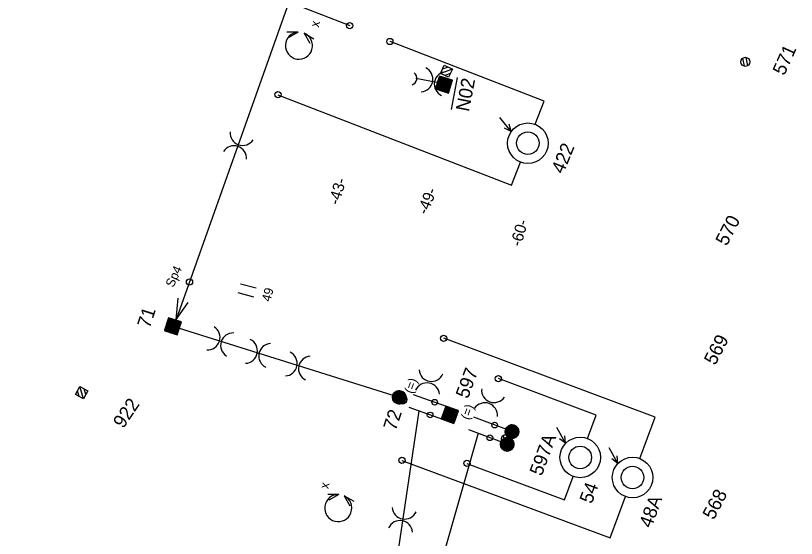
# Model space of a CAD drawing. Extents: x -595867 to -593796, y -1159595 to -1157495.
# Drawn here: x -594730.7 to -594644.3, y -1157983.3 to -1157925.4 of the extents above; entities that cross this region are included whole.
import ezdxf

# ---------------------------------------------------------------- set-up
doc = ezdxf.new("R2010")
doc.units = 0
for name, color, linetype in [('BVK_kanalizace_destova_nova', 7, 'Continuous'), ('BVK_kanalizace_jednotna_nova', 7, 'Continuous'), ('CD Telematika_novy', 7, 'Continuous')]:
    doc.layers.add(name, color=color, linetype=linetype)

# ---------------------------------------------------------------- blocks, each defined once
blk = doc.blocks.new('st_bp')
for p, q in [((0.0075, 0.0075), (-0.0075, 0.0075)), ((-0.0075, 0.0075), (-0.0075, -0.0075)), ((-0.0075, -0.0075), (0.0075, 0.0075)), ((-0.0075, -0.00708), (0.00708, 0.0075)), ((-0.0075, -0.00665), (0.00665, 0.0075)), ((-0.0075, -0.00623), (0.00623, 0.0075)), ((-0.0075, -0.0058), (0.0058, 0.0075)), ((-0.0075, -0.00538), (0.00538, 0.0075)), ((-0.0075, -0.00495), (0.00495, 0.0075)), ((-0.0075, -0.00453), (0.00453, 0.0075)), ((-0.0075, -0.00411), (0.00411, 0.0075)), ((-0.0075, -0.00368), (0.00368, 0.0075)), ((-0.0075, -0.00326), (0.00326, 0.0075)), ((-0.0075, -0.00283), (0.00283, 0.0075)), ((-0.0075, -0.00241), (0.00241, 0.0075)), ((-0.0075, -0.00198), (0.00198, 0.0075)), ((-0.0075, -0.00156), (0.00156, 0.0075)), ((-0.0075, -0.00114), (0.00114, 0.0075)), ((-0.0075, -0.00071), (0.00071, 0.0075)), ((-0.0075, -0.00029), (0.00029, 0.0075)), ((-0.0075, 0.00014), (-0.00014, 0.0075)), ((-0.0075, 0.00056), (-0.00056, 0.0075)), ((-0.0075, 0.00099), (-0.00099, 0.0075)), ((-0.0075, 0.00141), (-0.00141, 0.0075)), ((-0.0075, 0.00183), (-0.00183, 0.0075)), ((-0.0075, 0.00226), (-0.00226, 0.0075)), ((-0.0075, 0.00268), (-0.00268, 0.0075)), ((-0.0075, 0.00311), (-0.00311, 0.0075)), ((-0.0075, 0.00353), (-0.00353, 0.0075)), ((-0.0075, 0.00396), (-0.00396, 0.0075)), ((-0.0075, 0.00438), (-0.00438, 0.0075)), ((-0.0075, 0.0048), (-0.0048, 0.0075)), ((-0.0075, 0.00523), (-0.00523, 0.0075)), ((-0.0075, 0.00565), (-0.00565, 0.0075)), ((-0.0075, 0.00608), (-0.00608, 0.0075)), ((-0.0075, 0.0065), (-0.0065, 0.0075)), ((-0.0075, 0.00692), (-0.00692, 0.0075)), ((-0.0075, 0.00735), (-0.00735, 0.0075)), ((-0.00708, -0.0075), (0.0075, 0.00708)), ((-0.00665, -0.0075), (0.0075, 0.00665)), ((-0.00623, -0.0075), (0.0075, 0.00623)), ((-0.0058, -0.0075), (0.0075, 0.0058)), ((-0.00538, -0.0075), (0.0075, 0.00538)), ((-0.00495, -0.0075), (0.0075, 0.00495)), ((-0.00453, -0.0075), (0.0075, 0.00453)), ((-0.00411, -0.0075), (0.0075, 0.00411)), ((-0.00368, -0.0075), (0.0075, 0.00368)), ((-0.00326, -0.0075), (0.0075, 0.00326)), ((-0.00283, -0.0075), (0.0075, 0.00283)), ((-0.00241, -0.0075), (0.0075, 0.00241)), ((-0.00198, -0.0075), (0.0075, 0.00198)), ((-0.00156, -0.0075), (0.0075, 0.00156)), ((-0.00114, -0.0075), (0.0075, 0.00114)), ((-0.00071, -0.0075), (0.0075, 0.00071)), ((-0.00029, -0.0075), (0.0075, 0.00029)), ((0.0075, -0.0075), (0.0075, 0.0075)), ((-0.0075, -0.0075), (0.0075, -0.0075)), ((0.00014, -0.0075), (0.0075, -0.00014)), ((0.00056, -0.0075), (0.0075, -0.00056)), ((0.00099, -0.0075), (0.0075, -0.00099)), ((0.00141, -0.0075), (0.0075, -0.00141)), ((0.00183, -0.0075), (0.0075, -0.00183)), ((0.00226, -0.0075), (0.0075, -0.00226)), ((0.00268, -0.0075), (0.0075, -0.00268)), ((0.00311, -0.0075), (0.0075, -0.00311)), ((0.00353, -0.0075), (0.0075, -0.00353)), ((0.00396, -0.0075), (0.0075, -0.00396)), ((0.00438, -0.0075), (0.0075, -0.00438)), ((0.0048, -0.0075), (0.0075, -0.0048)), ((0.00523, -0.0075), (0.0075, -0.00523)), ((0.00565, -0.0075), (0.0075, -0.00565)), ((0.00608, -0.0075), (0.0075, -0.00608)), ((0.0065, -0.0075), (0.0075, -0.0065)), ((0.00692, -0.0075), (0.0075, -0.00692)), ((0.00735, -0.0075), (0.0075, -0.00735))]:
    blk.add_line(p, q)
blk = doc.blocks.new('st_2t')
for points in [[(-0.00779, 0.00818), (0.00247, 0.01437), (0.00322, 0.01403), (-0.00784, 0.00724)], [(-0.00784, 0.00724), (0.00322, 0.01403), (0.00405, 0.01352), (-0.0078, 0.00646)], [(-0.0078, 0.00646), (0.00405, 0.01352), (0.00485, 0.01287), (-0.00759, 0.00557)], [(-0.00767, 0.00906), (0.00148, 0.01469), (0.00247, 0.01437), (-0.00779, 0.00818)], [(-0.00748, 0.00968), (0.0002, 0.01491), (0.00148, 0.01469), (-0.00767, 0.00906)], [(-0.00759, 0.00557), (0.00485, 0.01287), (0.0055, 0.01208), (-0.00725, 0.00445)], [(-0.00727, 0.01041), (-0.00049, 0.01496), (0.0002, 0.01491), (-0.00748, 0.00968)], [(-0.00707, 0.01078), (-0.00187, 0.0148), (-0.00049, 0.01496), (-0.00727, 0.01041)], [(-0.00725, 0.00445), (0.0055, 0.01208), (0.00628, 0.01088), (-0.00676, 0.00361)], [(-0.00664, 0.0115), (-0.0026, 0.01461), (-0.00187, 0.0148), (-0.00707, 0.01078)], [(-0.00676, 0.00361), (0.00628, 0.01088), (0.00675, 0.00971), (-0.00604, 0.00259)], [(-0.00616, 0.01219), (-0.00352, 0.01422), (-0.0026, 0.01461), (-0.00664, 0.0115)], [(-0.00563, 0.0128), (-0.0045, 0.01371), (-0.00352, 0.01422), (-0.00616, 0.01219)], [(-0.00604, 0.00259), (0.00675, 0.00971), (0.00705, 0.00859), (-0.00525, 0.00183)], [(-0.00525, 0.00183), (0.00705, 0.00859), (0.00711, 0.00705), (-0.00442, 0.00118)], [(-0.00442, 0.00118), (0.00711, 0.00705), (0.00692, 0.00572), (-0.00354, 0.00068)], [(-0.00354, 0.00068), (0.00692, 0.00572), (0.00661, 0.00472), (-0.00243, 0.00029)], [(-0.00243, 0.00029), (0.00661, 0.00472), (0.00614, 0.00377), (-0.00151, 0.00007)], [(-0.00151, 0.00007), (0.00614, 0.00377), (0.00555, 0.00289), (-0.00086, 0)], [(-0.00086, 0), (0.00555, 0.00289), (0.00499, 0.00223), (0, 0)], [(0, 0), (0.00499, 0.00223), (0.00411, 0.0015), (0.001, 0.00008)], [(0.001, 0.00008), (0.00411, 0.0015), (0.00347, 0.00103), (0.00213, 0.00045)], [(0.00213, 0.00045), (0.00347, 0.00103), (0.00258, 0.00055), (0.00256, 0.00054)], [(-0.00779, -0.00682), (0.00247, -0.00063), (0.00322, -0.00097), (-0.00784, -0.00776)], [(-0.00784, -0.00776), (0.00322, -0.00097), (0.00405, -0.00148), (-0.0078, -0.00854)], [(-0.0078, -0.00854), (0.00405, -0.00148), (0.00485, -0.00213), (-0.00759, -0.00943)], [(-0.00767, -0.00594), (0.00148, -0.00031), (0.00247, -0.00063), (-0.00779, -0.00682)], [(-0.00748, -0.00532), (0.0002, -0.00009), (0.00148, -0.00031), (-0.00767, -0.00594)], [(-0.00759, -0.00943), (0.00485, -0.00213), (0.0055, -0.00292), (-0.00725, -0.01055)], [(-0.00727, -0.00459), (-0.00049, -0.00004), (0.0002, -0.00009), (-0.00748, -0.00532)], [(-0.00707, -0.00422), (-0.00187, -0.0002), (-0.00049, -0.00004), (-0.00727, -0.00459)], [(-0.00725, -0.01055), (0.0055, -0.00292), (0.00628, -0.00412), (-0.00676, -0.01139)], [(-0.00664, -0.0035), (-0.0026, -0.00039), (-0.00187, -0.0002), (-0.00707, -0.00422)], [(-0.00676, -0.01139), (0.00628, -0.00412), (0.00675, -0.00529), (-0.00604, -0.01241)], [(-0.00616, -0.00281), (-0.00352, -0.00078), (-0.0026, -0.00039), (-0.00664, -0.0035)], [(-0.00563, -0.0022), (-0.0045, -0.00129), (-0.00352, -0.00078), (-0.00616, -0.00281)], [(-0.00604, -0.01241), (0.00675, -0.00529), (0.00705, -0.00641), (-0.00525, -0.01317)], [(-0.00525, -0.01317), (0.00705, -0.00641), (0.00711, -0.00795), (-0.00442, -0.01382)], [(-0.00442, -0.01382), (0.00711, -0.00795), (0.00692, -0.00928), (-0.00354, -0.01432)], [(-0.00354, -0.01432), (0.00692, -0.00928), (0.00661, -0.01028), (-0.00243, -0.01471)], [(-0.00243, -0.01471), (0.00661, -0.01028), (0.00614, -0.01123), (-0.00151, -0.01493)], [(-0.00151, -0.01493), (0.00614, -0.01123), (0.00555, -0.01211), (-0.00086, -0.015)], [(-0.00086, -0.015), (0.00555, -0.01211), (0.00499, -0.01277), (0, -0.015)], [(0, -0.015), (0.00499, -0.01277), (0.00411, -0.0135), (0.001, -0.01492)], [(0.001, -0.01492), (0.00411, -0.0135), (0.00347, -0.01397), (0.00213, -0.01455)], [(0.00213, -0.01455), (0.00347, -0.01397), (0.00258, -0.01445), (0.00256, -0.01446)]]:
    blk.add_lwpolyline(points, close=True)
for centre in [(-0.00037, 0.00747), (-0.00037, -0.00753)]:
    blk.add_circle(centre, 0.0075)
blk = doc.blocks.new('st_tecka')
blk.add_circle((0, 0), 0.00314)
blk = doc.blocks.new('st2k_2t')
for p, q in [((-0.00037, 0.00747), (0.04494, 0.00747)), ((-0.00037, -0.00753), (0.04494, -0.00753))]:
    blk.add_line(p, q)
blk.add_blockref('st_2t', (0, 0))
at = {"rotation": 90}
for p in [(0.02017, 0.00747), (0.02017, -0.00753)]:
    blk.add_blockref('st_tecka', p, dxfattribs=at)
blk = doc.blocks.new('st2k_bp')
for p, q in [((0, 0.0075), (0.04531, 0.0075)), ((0, -0.0075), (0.04531, -0.0075))]:
    blk.add_line(p, q)
at = {"rotation": 90}
for p in [(0.02054, 0.0075), (0.02054, -0.0075)]:
    blk.add_blockref('st_tecka', p, dxfattribs=at)
blk.add_blockref('st_bp', (0, 0))
blk = doc.blocks.new('st_1t')
for points in [[(-0.00742, 0.00071), (0.00284, 0.0069), (0.00359, 0.00656), (-0.00747, -0.00023)], [(-0.00747, -0.00023), (0.00359, 0.00656), (0.00442, 0.00605), (-0.00743, -0.00101)], [(-0.00743, -0.00101), (0.00442, 0.00605), (0.00522, 0.0054), (-0.00722, -0.0019)], [(-0.00729, 0.00159), (0.00185, 0.00722), (0.00284, 0.0069), (-0.00742, 0.00071)], [(-0.00711, 0.00221), (0.00057, 0.00744), (0.00185, 0.00722), (-0.00729, 0.00159)], [(-0.00722, -0.0019), (0.00522, 0.0054), (0.00588, 0.00461), (-0.00688, -0.00302)], [(-0.00689, 0.00294), (-0.00011, 0.00749), (0.00057, 0.00744), (-0.00711, 0.00221)], [(-0.00669, 0.00331), (-0.00149, 0.00733), (-0.00011, 0.00749), (-0.00689, 0.00294)], [(-0.00688, -0.00302), (0.00588, 0.00461), (0.00666, 0.00341), (-0.00639, -0.00386)], [(-0.00627, 0.00403), (-0.00222, 0.00714), (-0.00149, 0.00733), (-0.00669, 0.00331)], [(-0.00639, -0.00386), (0.00666, 0.00341), (0.00712, 0.00224), (-0.00567, -0.00488)], [(-0.00579, 0.00472), (-0.00315, 0.00675), (-0.00222, 0.00714), (-0.00627, 0.00403)], [(-0.00526, 0.00533), (-0.00413, 0.00624), (-0.00315, 0.00675), (-0.00579, 0.00472)], [(-0.00567, -0.00488), (0.00712, 0.00224), (0.00742, 0.00112), (-0.00488, -0.00564)], [(-0.00488, -0.00564), (0.00742, 0.00112), (0.00748, -0.00042), (-0.00405, -0.00629)], [(-0.00405, -0.00629), (0.00748, -0.00042), (0.00729, -0.00175), (-0.00317, -0.00679)], [(-0.00317, -0.00679), (0.00729, -0.00175), (0.00698, -0.00275), (-0.00206, -0.00718)], [(-0.00206, -0.00718), (0.00698, -0.00275), (0.00651, -0.0037), (-0.00114, -0.0074)], [(-0.00114, -0.0074), (0.00651, -0.0037), (0.00592, -0.00458), (-0.00048, -0.00747)], [(-0.00048, -0.00747), (0.00592, -0.00458), (0.00536, -0.00524), (0.00037, -0.00747)], [(0.00037, -0.00747), (0.00536, -0.00524), (0.00449, -0.00597), (0.00138, -0.00739)], [(0.00138, -0.00739), (0.00449, -0.00597), (0.00384, -0.00644), (0.0025, -0.00702)], [(0.0025, -0.00702), (0.00384, -0.00644), (0.00295, -0.00692), (0.00293, -0.00693)]]:
    blk.add_lwpolyline(points, close=True)
blk.add_circle((0, 0), 0.0075)
blk = doc.blocks.new('pol_izol')
for centre, start, end in [((-0.01484, 0), 284.40471, 75.59529), ((0.01484, 0), 104.40471, 255.59529)]:
    blk.add_arc(centre, 0.01384, start, end)
blk = doc.blocks.new('kotv_tecka')
blk.add_circle((0, 0), 0.00345)
blk = doc.blocks.new('kotv_pev')
blk.add_line((0, 0), (-0.02299, -0.00565))
blk.add_lwpolyline([(0, 0), (-0.02214, 0.00639)])
blk.add_blockref('kotv_tecka', (-0.04416, 0))
blk = doc.blocks.new('pol_sipka2')
for q in [(0.01228, 0.00302), (0.01182, -0.00341)]:
    blk.add_line((0, 0), q)
blk = doc.blocks.new('pol_delic')
for p, q in [((-0.005, -0.00902), (-0.005, 0.00902)), ((0.005, -0.00902), (0.005, 0.00902))]:
    blk.add_line(p, q)
blk = doc.blocks.new('pol_sipk')
for q in [(0.0257, 0.0306), (0.0048, 0.0163), (0.0152, 0.0076)]:
    blk.add_line((0, 0), q)
blk = doc.blocks.new('odp_mzap')
for radius in [0.045, 0.025]:
    blk.add_circle((0, 0), radius)
blk.add_blockref('pol_sipk', (0.0179, 0.0413))

msp = doc.modelspace()

# ---------------------------------------------------------------- linework, layer by layer
at = {"layer": 'BVK_kanalizace_destova_nova'}
for p, q in [((-594713.29, -1157959.79), (-594688.238, -1157967.659)), ((-594659.912, -1157969.851), (-594683.297, -1157961.129)), ((-594666.451, -1157969.625), (-594677.254, -1157965.596)), ((-594686.064, -1157969.17), (-594693.126, -1158016.239)), ((-594667.412, -1157972.202), (-594666.451, -1157969.625)), ((-594661.62, -1157974.431), (-594659.912, -1157969.851)), ((-594679.508, -1157971.641), (-594692.383, -1158016.491)), ((-594687.938, -1157974.635), (-594664.901, -1157983.227)), ((-594680.742, -1157974.968), (-594669.945, -1157978.995)), ((-594669.945, -1157978.995), (-594668.984, -1157976.418)), ((-594664.901, -1157983.227), (-594663.193, -1157978.647))]:
    msp.add_line(p, q, dxfattribs=at)
at = {"layer": 'BVK_kanalizace_jednotna_nova'}
for p, q in [((-594650.032, -1157931.013), (-594650.192, -1157930.114)), ((-594649.662, -1157930.955), (-594649.824, -1157930.043)), ((-594682.357, -1157931.337), (-594683.68, -1157931.826)), ((-594682.835, -1157931.114), (-594683.462, -1157931.346)), ((-594682.579, -1157931.818), (-594683.198, -1157932.047)), ((-594713.036, -1157960.443), (-594713.539, -1157959.127)), ((-594713.52, -1157960.227), (-594713.755, -1157959.61)), ((-594712.818, -1157959.964), (-594713.056, -1157959.339)), ((-594723.653, -1157967.575), (-594723.845, -1157966.943)), ((-594723.185, -1157967.824), (-594723.596, -1157966.476)), ((-594722.935, -1157967.361), (-594723.129, -1157966.721)), ((-594688.022, -1157968.393), (-594688.182, -1157967.494)), ((-594687.652, -1157968.335), (-594687.814, -1157967.423)), ((-594681.968, -1157969.357), (-594683.291, -1157969.846)), ((-594682.446, -1157969.134), (-594683.073, -1157969.366)), ((-594682.19, -1157969.838), (-594682.809, -1157970.067)), ((-594676.032, -1157971.822), (-594676.192, -1157970.923)), ((-594675.662, -1157971.764), (-594675.824, -1157970.852)), ((-594676.543, -1157972.753), (-594676.703, -1157971.854)), ((-594676.173, -1157972.695), (-594676.335, -1157971.783))]:
    msp.add_line(p, q, dxfattribs=at)
for points in [[(-594682.773, -1157932.242), (-594683.682, -1157931.824), (-594683.265, -1157930.916), (-594682.356, -1157931.334)], [(-594713.946, -1157960.036), (-594713.537, -1157959.124), (-594712.625, -1157959.531), (-594713.034, -1157960.445)], [(-594724.065, -1157967.355), (-594723.594, -1157966.473), (-594722.712, -1157966.943), (-594723.183, -1157967.826)], [(-594682.384, -1157970.262), (-594683.293, -1157969.844), (-594682.876, -1157968.936), (-594681.967, -1157969.354)]]:
    msp.add_lwpolyline(points, close=True, dxfattribs=at)
for points in [[(-594682.773, -1157932.242), (-594683.682, -1157931.824), (-594683.265, -1157930.916), (-594682.356, -1157931.334), (-594682.773, -1157932.242)], [(-594713.946, -1157960.036), (-594713.537, -1157959.124), (-594712.625, -1157959.531), (-594713.034, -1157960.445), (-594713.946, -1157960.036)], [(-594724.065, -1157967.355), (-594723.594, -1157966.473), (-594722.712, -1157966.943), (-594723.183, -1157967.826), (-594724.065, -1157967.355)], [(-594682.384, -1157970.262), (-594683.293, -1157969.844), (-594682.876, -1157968.936), (-594681.967, -1157969.354), (-594682.384, -1157970.262)]]:
    msp.add_lwpolyline(points, dxfattribs=at)
for centre in [(-594649.919, -1157930.53), (-594649.919, -1157930.53), (-594687.909, -1157967.91), (-594687.909, -1157967.91), (-594675.919, -1157971.339), (-594675.919, -1157971.339), (-594676.43, -1157972.27), (-594676.43, -1157972.27)]:
    msp.add_circle(centre, 0.5, dxfattribs=at)
at = {"layer": 'CD Telematika_novy'}
for p, q in [((-594748.045, -1157905.431), (-594693.698, -1157926.501)), ((-594699.001, -1157919.804), (-594712.931, -1157959.057)), ((-594672.195, -1157934.891), (-594689.258, -1157928.276)), ((-594684.074, -1157932.829), (-594686.402, -1157932.369)), ((-594682.439, -1157935.814), (-594681.772, -1157932.264)), ((-594701.657, -1157934.166), (-594675.8, -1157944.191)), ((-594673.184, -1157937.443), (-594672.195, -1157934.891)), ((-594675.8, -1157944.191), (-594674.81, -1157941.639))]:
    msp.add_line(p, q, dxfattribs=at)
for centre, radius, start, end in [((-594699.339, -1157928.739), 1.5, 93.58803, 67.70716), ((-594687.048, -1157932.347), 0.764, 288.11486, 51.57755), ((-594694.988, -1157979.92), 1.5, 87.54158, 64.33962)]:
    msp.add_arc(centre, radius, start, end, dxfattribs=at)

# ---------------------------------------------------------------- block references
at = {"layer": 'BVK_kanalizace_destova_nova'}
for name, p, xscale, yscale, rotation in [('kotv_pev', (-594712.931, -1157959.057), 100.00000000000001, 99.99999999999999, -109.53803612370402), ('st_bp', (-594713.29, -1157959.79), 100, 100, -17.762371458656), ('pol_izol', (-594708.042, -1157961.474), 100, 100, -17.464669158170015), ('kotv_tecka', (-594683.319, -1157961.121), 100, 99.99999999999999, 70.54704464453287), ('pol_izol', (-594703.866, -1157962.805), 100.00000000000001, 99.99999999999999, -11.182412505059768), ('pol_izol', (-594699.46, -1157964.201), 99.99999999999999, 100.00000000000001, -11.191960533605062), ('pol_izol', (-594684.913, -1157965.978), 100.00000000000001, 100, 80.46882867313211), ('kotv_tecka', (-594677.255, -1157965.6), 100, 99.99999999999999, 70.54704464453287), ('st_1t', (-594688.238, -1157967.659), 100.00000000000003, 99.99999999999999, 79.51685128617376), ('st2k_bp', (-594682.63, -1157969.6), 100, 100, 160.34869409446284), ('pol_izol', (-594678.242, -1157968.255), 100.00000000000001, 99.99999999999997, 70.0198436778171), ('st2k_2t', (-594676.055, -1157972.152), 100, 99.99999999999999, 159.22478666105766), ('odp_mzap', (-594668.198, -1157974.31), 50, 50.00000000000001, 69.54704464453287), ('odp_mzap', (-594662.406, -1157976.539), 50, 50.00000000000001, 69.54704464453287), ('kotv_tecka', (-594687.938, -1157974.635), 100, 99.99999999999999, 70.54704464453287), ('kotv_tecka', (-594680.742, -1157974.968), 100, 99.99999999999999, 70.54704464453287), ('pol_izol', (-594687.892, -1157981.219), 100.00000000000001, 99.99999999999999, 80.02247429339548)]:
    msp.add_blockref(name, p, dxfattribs=dict(at, xscale=xscale, yscale=yscale, rotation=rotation))
at = {"layer": 'CD Telematika_novy'}
for name, p, xscale, yscale, rotation in [('kotv_tecka', (-594693.718, -1157926.521), 99.99999999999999, 100.00000000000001, 69.80947331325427), ('pol_sipka2', (-594699.433, -1157927.242), 100.00000000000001, 99.99999999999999, -163.16069258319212), ('pol_sipka2', (-594698.77, -1157927.352), 100, -100, -46.04097426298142), ('kotv_tecka', (-594689.273, -1157928.282), 99.99999999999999, 100.00000000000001, 69.80947331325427), ('pol_izol', (-594684.431, -1157932.73), 100.00000000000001, 99.99999999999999, -10.53177666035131), ('st_bp', (-594683.282, -1157933.042), 100, 100.00000000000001, 72.33992024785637), ('kotv_tecka', (-594701.657, -1157934.166), 99.99999999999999, 100.00000000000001, 69.80947331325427), ('odp_mzap', (-594673.997, -1157939.541), 50, 50, 78.51685128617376), ('pol_izol', (-594706.053, -1157939.796), 99.99999999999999, 100, 71.31476994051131), ('pol_delic', (-594705.064, -1157955.853), 100.00000000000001, 99.99999999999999, 75.55992853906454), ('pol_sipka2', (-594694.923, -1157978.422), 99.99999999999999, 100, -163.49165731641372), ('pol_sipka2', (-594694.338, -1157978.568), 100, -100, -45.50339547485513)]:
    msp.add_blockref(name, p, dxfattribs=dict(at, xscale=xscale, yscale=yscale, rotation=rotation))

# ---------------------------------------------------------------- texts
at = {"layer": 'BVK_kanalizace_destova_nova'}
for s, height, rotation, p in [('-49-', 1.25, 68.3562, (-594685.145, -1157947.529)), ('-60-', 1.25, 74.37097, (-594674.764, -1157951.048)), ('Sp4', 1, 65.20671, (-594713.248, -1157955.571)), ('71', 1.5, 71.72911, (-594715.861, -1157960.098)), ('597', 1.5, 69.59652, (-594680.641, -1157967.9)), ('(=)', 1, 69.54187, (-594686.778, -1157967.322)), ('(=)', 1, 69.54187, (-594680.528, -1157970.225)), ('72', 1.5, 71.72911, (-594688.626, -1157971.434)), ('597A', 1.5, 69.59652, (-594672.464, -1157976.443)), ('54', 1.5, 69.68232, (-594666.93, -1157979.525)), ('48A', 1.5, 69.68232, (-594660.334, -1157982.209))]:
    msp.add_text(s, height=height, rotation=rotation, dxfattribs=at).set_placement(p)
at = {"layer": 'BVK_kanalizace_jednotna_nova'}
for s, rotation, p in [('571', 65.59844, (-594645.618, -1157932.129)), ('570', 62.62089, (-594651.984, -1157950.994)), ('569', 62.62089, (-594653.258, -1157964.197)), ('922', 56, (-594718.784, -1157971.194)), ('568', 62.62089, (-594653.416, -1157981.311))]:
    msp.add_text(s, height=1.5, rotation=rotation, dxfattribs=at).set_placement(p)
at = {"layer": 'CD Telematika_novy'}
for s, height, rotation, p in [('x', 1, 77.795, (-594697.133, -1157926.766)), ('N02', 1.5, 79.02055, (-594680.523, -1157936.109)), ('422', 1.5, 67.59071, (-594670.077, -1157943.014)), ('-43-', 1.25, 73.76306, (-594694.914, -1157946.45)), ('49', 1, 74.885, (-594702.514, -1157957.136)), ('x', 1, 77.795, (-594696.089, -1157977.851))]:
    msp.add_text(s, height=height, rotation=rotation, dxfattribs=at).set_placement(p)

doc.saveas('drawing.dxf')
